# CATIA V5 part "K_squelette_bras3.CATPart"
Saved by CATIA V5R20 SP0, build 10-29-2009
Part number: squelette_bras3
Publications: "Point_centre_liaison_pivot23", "Point.2", "Droite.1", "Droite.2", "Point.4", "Point_centre_liaison_pivot_rouleau", "Plan.1", "axe_pivot23", "Plan_référence", "Point_centre_liaison_pivot231", "Droite.4", "Plan.4", "Plan.5", "plan_glissière", "point_centre_liaison_glissière", "Plan.7"
Bounding box of the stored display mesh (mm): x 100 to 100, y -40 to 0, z 20 to 150
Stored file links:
  G:\Khaled_CFAO_2011\SIL\SIL_GR2\pfradet\pfradet\Khaled\CAD_ThinkMOTION\K_squelette_bras3.CATPart
  G:\Khaled_CFAO_2011\SIL\SIL_GR2\pfradet\pfradet\Khaled\CAD_ThinkMOTION\K_squelette.CATProduct
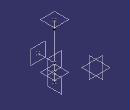
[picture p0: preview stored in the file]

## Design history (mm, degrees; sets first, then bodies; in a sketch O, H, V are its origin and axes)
Set1
  Point1 "Point_centre_liaison_pivot23": linked copy from another document
  Point2: linked copy from another document
  Point3 "Point_centre_liaison_pivot_rouleau": linked copy from another document
  Point4: linked copy from another document
  Plane1 "Plan_référence": linked copy from another document
  Point5 "Point_centre_liaison_pivot23": linked copy from another document
  Plane2 "plan_glissière": linked copy from another document
  Point6 "point_centre_liaison_glissière": linked copy from another document
  Plane3: linked copy from another document
Set2
  Line1: type PtPt, FirstPoint Point1, SecondPoint Point2
  Line2: type PtPt, FirstPoint Point3, SecondPoint Point4
  Plane4: type OffsetPt, RefPlane Plane1, RefPoint Point5
  Line3 "axe_pivot23": type Normal, RefPoint Point5, RefSkin Plane4, Start 0, End -20
  Line4: type Normal, RefPoint Point6, RefSkin Plane2, Start 0, End 20
  Plane5: type OffsetPt, RefPlane zx-plane, RefPoint Point3
  Plane6: type OffsetPt, RefPlane zx-plane, RefPoint Point4
Body1 (main body)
